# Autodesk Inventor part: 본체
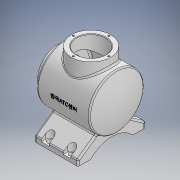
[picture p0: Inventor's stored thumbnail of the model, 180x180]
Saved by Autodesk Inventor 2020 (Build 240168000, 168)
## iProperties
Created: 2023-12
Part Number: 본체
Material: 일반
Document SubType Name: Modeling
Designer: 1강의실14
Density: 1 g/cm^3
Appearance: 기본값
Author: 1강의실14
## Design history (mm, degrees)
sketch "스케치1"
  geometry: L1 (-48.168, -50)-(48.168, -50); L2 (48.168, -50)-(48.168, 50); L3 (48.168, 50)-(-48.168, 50); L4 (-48.168, 50)-(-48.168, -50); L5 (-48.168, -50)-(48.168, 50); L6 (48.168, -50)-(-48.168, 50); L7 (-48.168, 0)-(59.832, 0); A1 r 113 centre (-53.168, 0) between (48.168, -50) and (48.168, 50); 1 further point
  constraints: 14 end point, 3 midpoint, 3 point on circle, 2 parallel, 1 centre point, 1 horizontal, 1 perpendicular
  dimensions: "d0" = 100 distance of L3.end L1.start; "d3" = 113 radius of A1; "d4" = 108 horizontal distance of L3.end L7.end
revolve "회전1" sketch "스케치1" stored, may be unused: angle "d5" = 90 deg
feature "쉘1" dims "d9" = 7
sketch "스케치2"
  geometry: C1 r 36 at (0, 0); 1 further point
  constraints: 1 centre point, 1 coincident
  dimensions: "d6" = 72 diameter of C1
extrude "돌출1" join sketch "스케치2" distance "d7" = 12; taper "d8" = 0 deg
sketch "스케치4"
  geometry: C1 r 27 at (0, 0); 1 further point
  constraints: 1 centre point, 1 coincident
  dimensions: "d11" = 54 diameter of C1
extrude "돌출2" cut sketch "스케치4" distance "d12" = 19; taper "d13" = 0 deg
sketch "스케치5"
  geometry: L1 (0, 0)-(0, 32.5)
  constraints: 2 end point, 1 vertical
  dimensions: "d14" = 32.5 distance of L1.start L1.end
hole "구멍1" sketch "스케치5" at (0, 32.5) diameter "d15" = 3.242; stored, may be unused: countersink angle "d19" = 90 deg, drill point angle "d21" = 118 deg; dims "d16" = 8, "d17" = 4, "d18" = 2, "d20" = 10
node "작업 평면1"
sketch "스케치7" dims "d11" = 54
  geometry: L1 (40.168, -62)-(-39.832, -62); L2 (-39.832, -62)-(-39.832, 62); L3 (-39.832, 62)-(40.168, 62); L4 (40.168, 62)-(40.168, -62); L5 (40.168, -62)-(-39.832, 62); L6 (-39.832, -62)-(40.168, 62); L7 (60.168, -36)-(60.168, 36) reference; 3 further points
  constraints: 12 end point, 4 midpoint, 2 parallel, 1 horizontal, 1 horizontal alignment, 1 perpendicular
  dimensions: "d26" = 124 distance of L1.end L2.end; "d27" = 80 distance of L2.end L3.end; "d82" = 20 distance between parallel lines of L7 L4
extrude "돌출3" join sketch "스케치7" distance "d28" = 10; taper "d29" = 0 deg
node "작업 평면2"
sketch "스케치8"
  geometry: L1 (-60.168, 36)-(-60.168, -36) reference; C1 r 36 at (1.832, 0); 1 further point
  constraints: 1 centre point, 1 horizontal alignment
  dimensions: "d31" = 72 diameter of C1; "d32" = 62 distance from line of L1 C1.centre
extrude "돌출4" join sketch "스케치8" stored distance "d33" = 10; taper "d34" = 0 deg
sketch "스케치9"
  geometry: C1 r 36 at (0, 0) reference; C2 r 27 at (0, 0); 1 further point
  constraints: 1 centre point, 1 coincident
  dimensions: "d35" = 54 diameter of C2
extrude "돌출5" cut sketch "스케치9" distance "d36" = 75.5; taper "d37" = 0 deg
sketch "스케치10"
  geometry: L1 (0, 0)-(32.5, 0); L2 (-43, 43)-(41.887, 43) reference; C1 r 27 at (0, 0) reference; C2 r 36 at (0, 0) reference; 1 further point
  constraints: 2 end point, 1 parallel
  dimensions: "d38" = 32.5 distance of L1.start L1.end
hole "구멍2" sketch "스케치10" at (32.5, 0) diameter "d39" = 3.242; stored, may be unused: countersink angle "d43" = 90 deg, drill point angle "d45" = 118 deg; dims "d40" = 8, "d41" = 4, "d42" = 2, "d44" = 10
sketch "스케치11"
  geometry: L1 (-67, 62)-(-67, -62) reference; L2 (-42.278, -26.694)-(-67, -62); L3 (-42.278, 26.694)-(-67, 62); L4 (-77, 62)-(-67, 62) reference; L5 (-77, -62)-(-67, -62) reference; A1 r 50 centre (0, 0) between (-42.278, -26.694) and (-42.278, 26.694) reference; 1 further point
  constraints: 4 end point, 2 point on circle
  dimensions: "d49" = 55 deg angle of L4 L3; "d51" = 55 deg angle of L5 L2
extrude "돌출6" join sketch "스케치11" stored distance "d52" = 80; taper "d53" = 0 deg
sketch "스케치12"
  geometry: L1 (124, 0)-(0, 0) reference; L2 (62, 0)-(62, 17); A1 r 52.096 centre (62, -35.096) between (100.5, 0) and (23.5, 0); 1 further point
  constraints: 3 point on circle, 2 end point, 2 point on line, 1 centre point, 1 midpoint, 1 vertical alignment
  dimensions: "d54" = 17 distance of L2.start L2.end; "d55" = 77 distance of A1.end A1.start
extrude "돌출7" cut sketch "스케치12" extent not by distance; stored distance "d56" = 0; taper "d57" = 0 deg
sketch "스케치14"
  geometry: L1 (-20.168, 62)-(-20.168, 54); L2 (-40.168, 62)-(39.832, 62) reference; L3 (-40.168, 38.5)-(-40.168, 62) reference; L4 (-40.168, 62)-(39.832, 62) reference; L5 (19.832, 62)-(19.832, 54); L6 (39.832, 62)-(39.832, 38.5) reference; C1 r 4.5 at (-20.168, 54); C2 r 4.5 at (19.832, 54); 1 further point
  constraints: 4 end point, 2 centre point, 2 coincident, 2 point on line, 2 vertical
  dimensions: "d58" = 8 distance of L1.start L1.end; "d59" = 20 distance between parallel lines of L3 L1; "d60" = 9 diameter of C1; "d61" = 8 distance of L5.start L5.end; "d62" = 20 distance between parallel lines of L6 L5; "d63" = 9 diameter of C2
extrude "돌출8" cut sketch "스케치14" distance "d64" = 42.5; taper "d65" = 0 deg
node "작업 평면3"
sketch "스케치15"
  geometry: L1 (-27.168, 54)-(-27.168, 62.253); L2 (-40, 62)-(39.832, 62) reference; L3 (-13.168, 54)-(-13.168, 62); L4 (12.832, 54)-(12.832, 62); L5 (26.832, 54)-(26.832, 62); C1 r 4.5 at (-20.168, 54) reference; C2 r 4.5 at (19.832, 54) reference; A1 r 7 centre (-20.168, 54) between (-27.168, 54) and (-13.168, 54); A2 r 7 centre (19.832, 54) between (12.832, 54) and (26.832, 54); 3 further points
  constraints: 8 end point, 4 point on circle, 3 point on line, 3 tangent, 2 centre point, 2 coincident, 2 perpendicular, 2 vertical, 1 horizontal alignment
  dimensions: "d67" = 14 diameter of A1; "d68" = 14 diameter of A2
extrude "돌출9" cut sketch "스케치15" distance "d69" = 26; taper "d70" = 0 deg
node "작업 평면4"
sketch "스케치16"
  geometry: L1 (-60.168, 36)-(-60.168, -36) reference; 2 further points
  constraints: 1 horizontal alignment, 1 other
  dimensions: "d71" = 62 distance from line of L1 point (1.832, 0)
feature "엠보싱1" sketch "스케치16" dims "d0" = 100, "d3" = 113, "d4" = 108, "d11" = 54, "d72" = 0.5, "d73" = 0
chamfer "모따기1" distance "d74" = 1; stored, may be unused: second distance "d75" = 2, angle "d76" = 45 deg
fillet "모깎기1" dims "d77" = 3
sketch "스케치17"
  geometry: L1 (-26.694, -42.278)-(-62, -67) reference; L2 (62, -67)-(26.083, -67) reference; L3 (-26.083, -67)-(-62, -67) reference; L4 (62, -67)-(26.694, -42.278) reference; A1 r 52.096 centre (0, -112.096) between (26.083, -67) and (-26.083, -67) reference; A2 r 50 centre (0, 0) between (-26.694, -42.278) and (26.694, -42.278) reference; 1 further point
  node "투영된 루프4"
sketch "스케치18"
  geometry: 1 further point
extrude "돌출10" join sketch "스케치17" stored distance "d83" = 10; taper "d84" = 0 deg
sketch "스케치19"
  geometry: L1 (26.083, -67)-(62, -67) reference; L2 (62, -67)-(26.694, -42.278) reference; L3 (-26.694, -42.278)-(-62, -67) reference; L4 (-62, -67)-(-26.083, -67) reference; A1 r 52.096 centre (0, -112.096) between (26.083, -67) and (-26.083, -67) reference; A2 r 50 centre (0, 0) between (-26.694, -42.278) and (26.694, -42.278) reference; 1 further point
extrude "돌출11" cut sketch "스케치19" stored distance "d85" = 10; taper "d86" = 0 deg
fillet "모깎기5" dims "d87" = 3
fillet "모깎기6" dims "d88" = 3
fillet "모깎기7" dims "d89" = 3
node "솔리드1"
pattern_circular "원형 패턴1" dims angle "d23" = 360 deg
pattern_circular "원형 패턴2" dims angle "d47" = 360 deg
mirror "미러1"
node "투영된 루프2"
node "투영된 루프3"
node "투영된 루프5"
feature "A9D066F2-1C7D-4E18-AEED-F7BC21143FA4" dims "d15" = 3.242, "d16" = 8, "d17" = 4, "d18" = 2, "d19" = 90 deg, "d20" = 10, "d21" = 118 deg
other parameters: "d25" = -77, "d30" = -142, "d66" = -6
